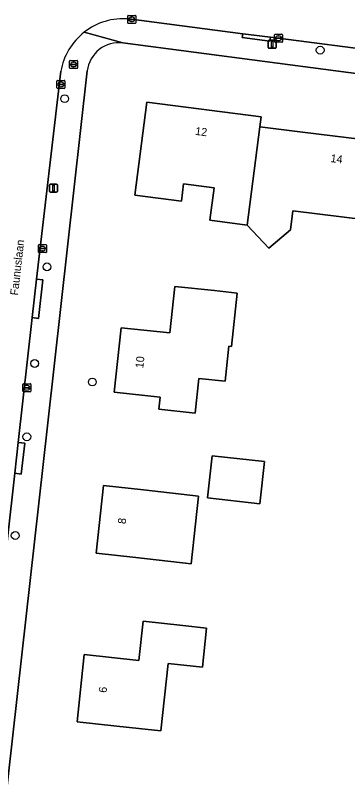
# Model space of a CAD drawing. Extents: x 162184 to 163154, y 385507 to 386516.
# Drawn here: x 162320 to 162361.5, y 385954.9 to 386050.9 of the extents above; entities that cross this region are included whole.
import ezdxf

# ---------------------------------------------------------------- set-up
doc = ezdxf.new("R2010")
doc.units = 0
for name, color, linetype in [('IMGEO_Boom', 7, 'Continuous'), ('IMGEO_Brandkraan', 7, 'Continuous'), ('IMGEO_Erf', 7, 'Continuous'), ('IMGEO_Kolk', 7, 'Continuous'), ('IMGEO_Lichtmast', 7, 'Continuous'), ('IMGEO_Openbare_ruimte_label', 7, 'Continuous'), ('IMGEO_Pand', 7, 'Continuous'), ('IMGEO_Pand_nummerreeks', 7, 'Continuous'), ('IMGEO_Rijbaan_lokaal_open', 7, 'Continuous'), ('IMGEO_Voetpad_open', 7, 'Continuous')]:
    doc.layers.add(name, color=color, linetype=linetype)

msp = doc.modelspace()

# ---------------------------------------------------------------- linework, layer by layer
at = {"layer": 'IMGEO_Boom'}
for centre in [(162358.09, 386046.577), (162326.148, 386040.515), (162323.935, 386019.494), (162322.39, 386007.422), (162329.602, 386005.102), (162321.415, 385998.262), (162319.959, 385985.92)]:
    msp.add_circle(centre, 0.489, dxfattribs=at)
at = {"layer": 'IMGEO_Brandkraan'}
for p, q in [((162326.764, 386044.366), (162326.764, 386045.218)), ((162326.839, 386045.292), (162327.691, 386045.292)), ((162327.023, 386044.786), (162327.023, 386044.798)), ((162327.461, 386044.749), (162327.063, 386044.749)), ((162327.066, 386044.835), (162327.464, 386044.835)), ((162327.275, 386044.512), (162327.25, 386044.512)), ((162327.252, 386045.072), (162327.277, 386045.072)), ((162327.507, 386044.798), (162327.507, 386044.786)), ((162327.765, 386045.218), (162327.765, 386044.366)), ((162327.691, 386044.292), (162326.839, 386044.292))]:
    msp.add_line(p, q, dxfattribs=at)
for points in [[(162326.764, 386044.366), (162326.764, 386045.218)], [(162326.839, 386045.292), (162327.691, 386045.292)], [(162327.765, 386045.218), (162327.765, 386044.366)], [(162327.691, 386044.292), (162326.839, 386044.292)]]:
    msp.add_lwpolyline(points, dxfattribs=at)
for centre, radius, start, end in [((162326.841, 386045.216), 0.0765, 91.55205, 178.44795), ((162326.841, 386045.216), 0.0765, 91.55205, 178.44795), ((162327.063, 386044.795), 0.0403, 85.87752, 175.75265), ((162327.06, 386044.785), 0.0366, 178.93798, 274.71019), ((162327.464, 386044.792), 0.043, 264.86636, 352.45326), ((162327.468, 386044.797), 0.0386, 1.73085, 96.63898), ((162327.689, 386045.216), 0.0765, 1.55205, 88.44795), ((162327.689, 386045.216), 0.0765, 1.55205, 88.44795), ((162326.841, 386044.368), 0.0765, 181.55205, 268.44795), ((162326.841, 386044.368), 0.0765, 181.55205, 268.44795), ((162327.689, 386044.368), 0.0765, 271.55205, 358.44795), ((162327.689, 386044.368), 0.0765, 271.55205, 358.44795)]:
    msp.add_arc(centre, radius, start, end, dxfattribs=at)
for centre, major_axis, ratio, start_param, end_param in [((162327.251, 386044.792), (-0.387, 0.002), 0.722429, 4.712389, 7.853982), ((162327.276, 386044.792), (-0.39, 0.002), 0.717154, 1.570796, 4.712389)]:
    msp.add_ellipse(centre, major_axis=major_axis, ratio=ratio, start_param=start_param, end_param=end_param, dxfattribs=at)
at = {"layer": 'IMGEO_Erf'}
for points in [[(162392.176, 386039.984), (162369.15, 386042.818), (162368.942, 386042.845), (162333.427, 386047.473)], [(162328.975, 386043.984), (162324.028, 386000), (162313.036, 385902.247)]]:
    msp.add_lwpolyline(points, dxfattribs=at)
for points in [[(162351.67, 386021.825), (162348.981, 386024.711), (162344.305, 386025.314), (162344.83, 386029.384), (162341.013, 386029.876), (162340.736, 386027.725), (162334.924, 386028.475), (162336.421, 386040.079), (162350.725, 386038.234), (162350.564, 386036.985), (162355.87, 386036.331), (162365.09, 386035.195), (162365.24, 386036.418), (162368.923, 386035.964), (162368.311, 386031.002), (162367.459, 386024.085), (162364.471, 386024.454), (162363.698, 386024.549), (162363.797, 386025.355), (162354.656, 386026.481), (162354.364, 386024.115)], [(162342.458, 386001.208), (162337.933, 386001.695), (162338.098, 386003.226), (162332.35, 386003.844), (162333.216, 386011.898), (162339.279, 386011.245), (162339.905, 386017.062), (162344.877, 386016.527), (162347.722, 386016.221), (162347.003, 386009.535), (162346.67, 386009.57), (162346.199, 386005.194), (162342.924, 386005.546)], [(162350.542, 385989.9), (162344.015, 385990.624), (162344.6, 385995.9), (162351.127, 385995.176)], [(162341.943, 385982.407), (162335.041, 385983.176), (162330.071, 385983.729), (162331.012, 385992.177), (162335.982, 385991.624), (162342.884, 385990.855)], [(162343.361, 385969.46), (162339.099, 385969.923), (162338.188, 385961.52), (162332.662, 385962.119), (162327.691, 385962.658), (162328.603, 385971.065), (162335.419, 385970.325), (162335.949, 385975.212), (162340.92, 385974.673), (162343.892, 385974.351)]]:
    msp.add_lwpolyline(points, close=True, dxfattribs=at)
msp.add_arc((162332.915, 386043.542), 3.964, 82.57389, 173.59719, dxfattribs=at)
at = {"layer": 'IMGEO_Kolk'}
for p, q in [((162334.028, 386049.999), (162334.028, 386050.851)), ((162334.103, 386050.925), (162334.955, 386050.925)), ((162334.287, 386050.419), (162334.287, 386050.431)), ((162334.725, 386050.382), (162334.327, 386050.382)), ((162334.33, 386050.468), (162334.728, 386050.468)), ((162334.516, 386050.705), (162334.541, 386050.705)), ((162334.771, 386050.431), (162334.771, 386050.419)), ((162335.029, 386050.851), (162335.029, 386049.999)), ((162334.955, 386049.925), (162334.103, 386049.925)), ((162334.539, 386050.145), (162334.514, 386050.145)), ((162352.388, 386047.644), (162352.388, 386048.496)), ((162352.463, 386048.57), (162353.315, 386048.57)), ((162352.876, 386048.35), (162352.901, 386048.35)), ((162353.389, 386048.496), (162353.389, 386047.644)), ((162353.315, 386047.57), (162352.463, 386047.57)), ((162352.647, 386048.064), (162352.647, 386048.076)), ((162353.085, 386048.027), (162352.687, 386048.027)), ((162352.69, 386048.113), (162353.088, 386048.113)), ((162352.899, 386047.79), (162352.874, 386047.79)), ((162353.131, 386048.076), (162353.131, 386048.064)), ((162325.172, 386041.863), (162325.172, 386042.715)), ((162325.247, 386042.789), (162326.099, 386042.789)), ((162325.66, 386042.569), (162325.685, 386042.569)), ((162326.173, 386042.715), (162326.173, 386041.863)), ((162326.099, 386041.789), (162325.247, 386041.789)), ((162325.431, 386042.283), (162325.431, 386042.295)), ((162325.869, 386042.246), (162325.471, 386042.246)), ((162325.474, 386042.332), (162325.872, 386042.332)), ((162325.683, 386042.009), (162325.658, 386042.009)), ((162325.915, 386042.295), (162325.915, 386042.283)), ((162322.865, 386021.351), (162322.865, 386022.203)), ((162322.94, 386022.277), (162323.792, 386022.277)), ((162323.124, 386021.771), (162323.124, 386021.783)), ((162323.562, 386021.734), (162323.164, 386021.734)), ((162323.167, 386021.82), (162323.565, 386021.82)), ((162323.376, 386021.497), (162323.351, 386021.497)), ((162323.353, 386022.057), (162323.378, 386022.057)), ((162323.608, 386021.783), (162323.608, 386021.771)), ((162323.866, 386022.203), (162323.866, 386021.351)), ((162323.792, 386021.277), (162322.94, 386021.277)), ((162320.92, 386003.959), (162320.92, 386004.811)), ((162320.995, 386004.885), (162321.847, 386004.885)), ((162321.179, 386004.379), (162321.179, 386004.391)), ((162321.617, 386004.342), (162321.219, 386004.342)), ((162321.222, 386004.428), (162321.62, 386004.428)), ((162321.431, 386004.105), (162321.406, 386004.105)), ((162321.408, 386004.665), (162321.433, 386004.665)), ((162321.663, 386004.391), (162321.663, 386004.379)), ((162321.921, 386004.811), (162321.921, 386003.959)), ((162321.847, 386003.885), (162320.995, 386003.885))]:
    msp.add_line(p, q, dxfattribs=at)
for points in [[(162334.028, 386049.999), (162334.028, 386050.851)], [(162334.103, 386050.925), (162334.955, 386050.925)], [(162335.029, 386050.851), (162335.029, 386049.999)], [(162334.955, 386049.925), (162334.103, 386049.925)], [(162352.388, 386047.644), (162352.388, 386048.496)], [(162352.463, 386048.57), (162353.315, 386048.57)], [(162353.389, 386048.496), (162353.389, 386047.644)], [(162353.315, 386047.57), (162352.463, 386047.57)], [(162325.172, 386041.863), (162325.172, 386042.715)], [(162325.247, 386042.789), (162326.099, 386042.789)], [(162326.173, 386042.715), (162326.173, 386041.863)], [(162326.099, 386041.789), (162325.247, 386041.789)], [(162322.865, 386021.351), (162322.865, 386022.203)], [(162322.94, 386022.277), (162323.792, 386022.277)], [(162323.866, 386022.203), (162323.866, 386021.351)], [(162323.792, 386021.277), (162322.94, 386021.277)], [(162320.92, 386003.959), (162320.92, 386004.811)], [(162320.995, 386004.885), (162321.847, 386004.885)], [(162321.921, 386004.811), (162321.921, 386003.959)], [(162321.847, 386003.885), (162320.995, 386003.885)]]:
    msp.add_lwpolyline(points, dxfattribs=at)
for centre, radius, start, end in [((162334.105, 386050.849), 0.0765, 91.55205, 178.44795), ((162334.105, 386050.849), 0.0765, 91.55205, 178.44795), ((162334.327, 386050.428), 0.0403, 85.87752, 175.75265), ((162334.324, 386050.418), 0.0366, 178.93798, 274.71019), ((162334.728, 386050.425), 0.043, 264.86636, 352.45326), ((162334.732, 386050.43), 0.0386, 1.73085, 96.63898), ((162334.953, 386050.849), 0.0765, 1.55205, 88.44795), ((162334.953, 386050.849), 0.0765, 1.55205, 88.44795), ((162334.105, 386050.001), 0.0765, 181.55205, 268.44795), ((162334.105, 386050.001), 0.0765, 181.55205, 268.44795), ((162334.953, 386050.001), 0.0765, 271.55205, 358.44795), ((162334.953, 386050.001), 0.0765, 271.55205, 358.44795), ((162352.465, 386048.494), 0.0765, 91.55205, 178.44795), ((162352.465, 386048.494), 0.0765, 91.55205, 178.44795), ((162353.313, 386048.494), 0.0765, 1.55205, 88.44795), ((162353.313, 386048.494), 0.0765, 1.55205, 88.44795), ((162352.465, 386047.646), 0.0765, 181.55205, 268.44795), ((162352.465, 386047.646), 0.0765, 181.55205, 268.44795), ((162352.687, 386048.073), 0.0403, 85.87752, 175.75265), ((162352.684, 386048.063), 0.0366, 178.93798, 274.71019), ((162353.088, 386048.07), 0.043, 264.86636, 352.45326), ((162353.092, 386048.075), 0.0386, 1.73085, 96.63898), ((162353.313, 386047.646), 0.0765, 271.55205, 358.44795), ((162353.313, 386047.646), 0.0765, 271.55205, 358.44795), ((162325.249, 386042.713), 0.0765, 91.55205, 178.44795), ((162325.249, 386042.713), 0.0765, 91.55205, 178.44795), ((162326.097, 386042.713), 0.0765, 1.55205, 88.44795), ((162326.097, 386042.713), 0.0765, 1.55205, 88.44795), ((162325.249, 386041.865), 0.0765, 181.55205, 268.44795), ((162325.249, 386041.865), 0.0765, 181.55205, 268.44795), ((162325.471, 386042.292), 0.0403, 85.87752, 175.75265), ((162325.468, 386042.282), 0.0366, 178.93798, 274.71019), ((162325.872, 386042.289), 0.043, 264.86636, 352.45326), ((162325.876, 386042.294), 0.0386, 1.73085, 96.63898), ((162326.097, 386041.865), 0.0765, 271.55205, 358.44795), ((162326.097, 386041.865), 0.0765, 271.55205, 358.44795), ((162322.942, 386022.201), 0.0765, 91.55205, 178.44795), ((162322.942, 386022.201), 0.0765, 91.55205, 178.44795), ((162323.164, 386021.78), 0.0403, 85.87752, 175.75265), ((162323.161, 386021.77), 0.0366, 178.93798, 274.71019), ((162323.565, 386021.777), 0.043, 264.86636, 352.45326), ((162323.569, 386021.782), 0.0386, 1.73085, 96.63898), ((162323.79, 386022.201), 0.0765, 1.55205, 88.44795), ((162323.79, 386022.201), 0.0765, 1.55205, 88.44795), ((162322.942, 386021.353), 0.0765, 181.55205, 268.44795), ((162322.942, 386021.353), 0.0765, 181.55205, 268.44795), ((162323.79, 386021.353), 0.0765, 271.55205, 358.44795), ((162323.79, 386021.353), 0.0765, 271.55205, 358.44795), ((162320.997, 386004.809), 0.0765, 91.55205, 178.44795), ((162320.997, 386004.809), 0.0765, 91.55205, 178.44795), ((162321.219, 386004.388), 0.0403, 85.87752, 175.75265), ((162321.216, 386004.378), 0.0366, 178.93798, 274.71019), ((162321.62, 386004.385), 0.043, 264.86636, 352.45326), ((162321.624, 386004.39), 0.0386, 1.73085, 96.63898), ((162321.845, 386004.809), 0.0765, 1.55205, 88.44795), ((162321.845, 386004.809), 0.0765, 1.55205, 88.44795), ((162320.997, 386003.961), 0.0765, 181.55205, 268.44795), ((162320.997, 386003.961), 0.0765, 181.55205, 268.44795), ((162321.845, 386003.961), 0.0765, 271.55205, 358.44795), ((162321.845, 386003.961), 0.0765, 271.55205, 358.44795)]:
    msp.add_arc(centre, radius, start, end, dxfattribs=at)
for centre, major_axis, ratio, start_param, end_param in [((162334.515, 386050.425), (-0.387, 0.002), 0.722429, 4.712389, 7.853982), ((162334.54, 386050.425), (-0.39, 0.002), 0.717154, 1.570796, 4.712389), ((162352.875, 386048.07), (-0.387, 0.002), 0.722429, 4.712389, 7.853982), ((162352.9, 386048.07), (-0.39, 0.002), 0.717154, 1.570796, 4.712389), ((162325.659, 386042.289), (-0.387, 0.002), 0.722429, 4.712389, 7.853982), ((162325.684, 386042.289), (-0.39, 0.002), 0.717154, 1.570796, 4.712389), ((162323.352, 386021.777), (-0.387, 0.002), 0.722429, 4.712389, 7.853982), ((162323.377, 386021.777), (-0.39, 0.002), 0.717154, 1.570796, 4.712389), ((162321.407, 386004.385), (-0.387, 0.002), 0.722429, 4.712389, 7.853982), ((162321.432, 386004.385), (-0.39, 0.002), 0.717154, 1.570796, 4.712389)]:
    msp.add_ellipse(centre, major_axis=major_axis, ratio=ratio, start_param=start_param, end_param=end_param, dxfattribs=at)
at = {"layer": 'IMGEO_Lichtmast'}
for p, q in [((162351.6, 386046.906), (162351.6, 386047.706)), ((162351.6, 386047.706), (162351.6, 386046.906)), ((162351.7, 386047.806), (162352.49, 386047.806)), ((162352.49, 386047.806), (162351.7, 386047.806)), ((162352.59, 386047.706), (162352.59, 386046.906)), ((162352.59, 386046.906), (162352.59, 386047.706)), ((162352.49, 386046.806), (162351.7, 386046.806)), ((162351.7, 386046.806), (162352.49, 386046.806)), ((162324.244, 386028.931), (162324.244, 386029.731)), ((162324.244, 386029.731), (162324.244, 386028.931)), ((162324.344, 386029.831), (162325.134, 386029.831)), ((162325.134, 386029.831), (162324.344, 386029.831)), ((162325.234, 386029.731), (162325.234, 386028.931)), ((162325.234, 386028.931), (162325.234, 386029.731)), ((162325.134, 386028.831), (162324.344, 386028.831)), ((162324.344, 386028.831), (162325.134, 386028.831))]:
    msp.add_line(p, q, dxfattribs=at)
for points in [[(162352.02, 386047.681), (162352.17, 386047.681), (162352.17, 386046.931), (162352.02, 386046.931), (162352.02, 386047.681)], [(162324.664, 386029.706), (162324.814, 386029.706), (162324.814, 386028.956), (162324.664, 386028.956), (162324.664, 386029.706)]]:
    msp.add_lwpolyline(points, dxfattribs=at)
for centre, start, end in [((162351.7, 386047.706), 90, 180), ((162351.7, 386047.706), 90, 180), ((162352.49, 386047.706), 0, 90), ((162352.49, 386047.706), 360, 90), ((162351.7, 386046.906), 180, 270), ((162351.7, 386046.906), 180, 270), ((162352.49, 386046.906), 270, 0), ((162352.49, 386046.906), 270, 0), ((162324.344, 386029.731), 90, 180), ((162324.344, 386029.731), 90, 180), ((162325.134, 386029.731), 0, 90), ((162325.134, 386029.731), 360, 90), ((162324.344, 386028.931), 180, 270), ((162324.344, 386028.931), 180, 270), ((162325.134, 386028.931), 270, 0), ((162325.134, 386028.931), 270, 0)]:
    msp.add_arc(centre, 0.1, start, end, dxfattribs=at)
at = {"layer": 'IMGEO_Pand'}
for points in [[(162350.564, 386036.985), (162350.725, 386038.234), (162336.421, 386040.079), (162334.924, 386028.475), (162340.736, 386027.725), (162341.013, 386029.876), (162344.83, 386029.384), (162344.305, 386025.314), (162348.981, 386024.711)], [(162348.981, 386024.711), (162351.67, 386021.825), (162354.364, 386024.115), (162354.656, 386026.481), (162363.797, 386025.355), (162363.698, 386024.549), (162364.471, 386024.454), (162367.459, 386024.085), (162368.311, 386031.002), (162368.923, 386035.964), (162365.24, 386036.418), (162365.09, 386035.195), (162355.87, 386036.331), (162350.564, 386036.985)], [(162342.458, 386001.208), (162342.924, 386005.546), (162346.199, 386005.194), (162346.67, 386009.57), (162347.003, 386009.535), (162347.722, 386016.221), (162344.877, 386016.527), (162339.905, 386017.062), (162339.279, 386011.245), (162333.216, 386011.898), (162332.35, 386003.844), (162338.098, 386003.226), (162337.933, 386001.695)], [(162351.127, 385995.176), (162344.6, 385995.9), (162344.015, 385990.624), (162350.542, 385989.9)], [(162331.012, 385992.177), (162330.071, 385983.729), (162335.041, 385983.176), (162341.943, 385982.407), (162342.884, 385990.855), (162335.982, 385991.624)], [(162338.188, 385961.52), (162339.099, 385969.923), (162343.361, 385969.46), (162343.892, 385974.351), (162340.92, 385974.673), (162335.949, 385975.212), (162335.419, 385970.325), (162328.603, 385971.065), (162327.691, 385962.658), (162332.662, 385962.119)]]:
    msp.add_lwpolyline(points, close=True, dxfattribs=at)
at = {"layer": 'IMGEO_Rijbaan_lokaal_open'}
for points in [[(162334.156, 386050.473), (162348.417, 386048.635), (162351.863, 386048.191), (162366.674, 386046.283), (162370.348, 386045.809), (162373.192, 386045.443), (162376.799, 386044.978), (162392.559, 386042.947), (162410.449, 386040.733)], [(162314.938, 385949.347), (162315.696, 385956.099), (162317.692, 385973.893), (162318.116, 385977.668), (162319.915, 385993.698), (162320.347, 385997.546), (162322.098, 386013.153), (162322.638, 386017.967), (162325.667, 386043.936)]]:
    msp.add_lwpolyline(points, dxfattribs=at)
for centre, radius, start, end in [((162333.463, 386042.594), 7.909, 84.97216, 128.06738), ((162333.463, 386042.592), 7.911, 128.05946, 170.22024)]:
    msp.add_arc(centre, radius, start, end, dxfattribs=at)
at = {"layer": 'IMGEO_Voetpad_open'}
for points in [[(162376.799, 386044.978), (162376.737, 386044.495), (162373.13, 386044.963), (162373.192, 386045.443), (162370.348, 386045.809), (162370.287, 386045.332), (162369.329, 386045.456), (162366.613, 386045.807), (162366.674, 386046.283), (162351.863, 386048.191), (162351.8, 386047.707), (162348.354, 386048.149), (162348.417, 386048.635), (162334.156, 386050.473)], [(162328.586, 386048.821), (162333.427, 386047.473), (162368.942, 386042.845), (162369.15, 386042.818), (162392.176, 386039.984), (162396.869, 386039.674)], [(162333.427, 386047.473), (162328.586, 386048.821)], [(162325.667, 386043.936), (162322.638, 386017.967), (162323.428, 386017.878), (162322.889, 386013.064), (162322.098, 386013.153), (162320.347, 385997.546), (162321.149, 385997.456), (162320.72, 385993.607), (162319.915, 385993.698), (162318.116, 385977.668), (162318.915, 385977.577), (162318.488, 385973.802), (162317.692, 385973.893), (162315.696, 385956.099), (162316.488, 385956.004), (162315.731, 385949.252), (162314.938, 385949.347), (162313.306, 385934.616), (162314.069, 385934.525), (162313.303, 385927.738), (162312.557, 385927.828), (162309.432, 385898.029), (162315.549, 385899.101)], [(162324.028, 386000), (162328.975, 386043.984)], [(162313.036, 385902.247), (162324.028, 386000)]]:
    msp.add_lwpolyline(points, dxfattribs=at)
for points in [[(162351.863, 386048.191), (162348.417, 386048.635), (162348.354, 386048.149), (162351.8, 386047.707)], [(162323.428, 386017.878), (162322.638, 386017.967), (162322.098, 386013.153), (162322.889, 386013.064)], [(162321.149, 385997.456), (162320.347, 385997.546), (162319.915, 385993.698), (162320.72, 385993.607)]]:
    msp.add_lwpolyline(points, close=True, dxfattribs=at)
for centre, radius, start, end in [((162333.463, 386042.594), 7.909, 84.97216, 128.06738), ((162333.463, 386042.592), 7.911, 128.05946, 170.22024), ((162332.915, 386043.542), 3.964, 82.57389, 173.59719)]:
    msp.add_arc(centre, radius, start, end, dxfattribs=at)

# ---------------------------------------------------------------- texts
at = {"layer": 'IMGEO_Openbare_ruimte_label'}
msp.add_text('Faunuslaan', height=1, rotation=83.57125, dxfattribs=at).set_placement((162320.313, 386015.891))
at = {"layer": 'IMGEO_Pand_nummerreeks'}
for s, rotation, p in [('12', 352.65029, (162342.421, 386035.998)), ('14', 352.97596, (162359.348, 386032.598)), ('10', 83.86289, (162335.966, 386006.793)), ('8', 83.64418, (162333.772, 385987.32)), ('6', 83.80871, (162331.378, 385966.234))]:
    msp.add_text(s, height=1, rotation=rotation, dxfattribs=at).set_placement(p)

doc.saveas('drawing.dxf')
